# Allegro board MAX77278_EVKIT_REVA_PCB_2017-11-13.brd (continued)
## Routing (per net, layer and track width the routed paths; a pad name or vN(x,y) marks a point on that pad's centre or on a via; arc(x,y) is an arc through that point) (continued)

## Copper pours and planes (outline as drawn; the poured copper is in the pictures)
VBATT on TOP: 53.34,3.94 53.34,8 54.48,9.14 56.26,9.14 57.28,10.16 57.28,12.45 53.09,12.45 50.29,9.65 50.29,3.94
VBATT on INTERNAL2: 51.08,39.52 50.77,39.52 50.27,39.01 50.27,38.4 50.5,38.4 50.72,38.76 51.13,38.76 51.32,38.95 51.32,39.25 51.31,39.42 51.23,39.47
VBATT on INTERNAL3: 50.29,39.24 50.67,39.24 57.53,32.38 57.53,9.53 53.09,5.08 53.09,3.68 51.31,3.68 51.31,13.72 48.77,16.26 48.77,37.59 49.53,38.35 50.16,39.12
BST on TOP: 55.24,38.99 55.24,37.34 56.13,37.34 56.13,38.99
CHGIN on TOP: 48.49,40.77 49.71,40.77 49.96,40.51 49.96,40.44 49.53,40.01 48.49,40.01
CHGIN on TOP: 36.78,12.47 36.78,9.5 45.11,9.5 45.11,12.47
CHGIN on INTERNAL2: 49.15,40.74 50.09,40.74 50.11,40.72 50.11,40.23 49.56,39.67 48.49,39.67 48.49,40.08
CHGIN on INTERNAL3: 39.37,9.4 39.37,37.19 41.5,39.32 47.19,39.32 48.08,40.21 49.43,40.21 49.43,39.75 49.15,39.75 48.84,39.45 48.84,39.04 48.01,38.1 48.01,16.26 44.96,13.21 44.96,9.4
CS on TOP: 51.71,44.88 51.71,43.76 51.84,43.64 51.84,42.82 52.1,42.82 53.31,44.04 53.31,44.88
GROUND on TOP: 0.25,0.51 0.25,98.3 100.33,98.3 100.2,0.46 ; 16 cut-outs
GROUND on BOTTOM: 0.36,95.76 0.36,0.53 100.66,0.53 100.66,95.76 ; 31 cut-outs
GROUND on INTERNAL2: 11.84,0.81 0,0.76 0,96.27 100.5,96.27 100.43,0.81 ; 1 cut-out
IBATT_SNS on BOTTOM: 60.83,4.57 60.83,4.58 53.38,4.58 53.38,7.21 53.46,7.3 61.24,7.27 66.29,12.32 68.58,12.32 71.24,9.66 77.36,9.66 79.35,9.65 80,9 80.02,8.09 78.54,8.09 78.08,7.64 77.34,7.64 77.34,7.62 74.29,4.57
IN_SBB on TOP: 60.45,14.22 60.45,9.53 63.12,9.53 63.12,14.22
IN_SBB on BOTTOM: 51.59,40.54 51.59,39.12 52.7,39.12 52.7,40.54
IN_SBB on INTERNAL2: 51.69,40.21 51.69,40.17 51.36,39.84 51.36,39.46 51.79,39.04 52,39.04 52.26,39.29 52.26,39.85 51.89,40.21 51.7,40.21
IN_SBB on INTERNAL3: 58.04,32.13 51.31,38.86 51.31,39.88 51.69,40.26 52.83,40.26 62.36,30.73 62.36,24 63.63,22.61 63.63,9.53 58.04,9.53
INLDO on TOP: 55.52,42.44 55.52,43.41 66.52,54.41 80.72,54.41 81.66,55.35 84.56,55.35 84.56,52.53 84.53,52.5 79.25,52.5 79.04,52.7 66.93,52.7 56.67,42.44
LDO on TOP: 77.72,60.2 77.72,58.93 80.64,58.93 80.64,60.2
LDO on TOP: 53.37,43.05 53.37,43.26 53.82,43.71 53.82,44.42 54.28,44.88 54.28,45.03 54.41,45.16 54.41,45.67 54.61,45.87 54.61,46.99 67.82,60.2 80.95,60.22 80.98,60.2 81.05,60.2 81.79,60.93 88.65,60.93 89.2,60.38 91.67,60.38 91.67,57.45 88.26,57.45 87.53,58.19 68.83,58.17 56.39,45.72 55.27,45.72 55.27,45.62 55.22,45.57 55.09,45.57 54.81,45.29 54.81,44.78 54.58,44.55 54.58,44.09 54.18,43.69 54.18,43.18 54.05,43.05
LXA on TOP: 51.31,37.47 51.41,37.62 51.82,38.02 51.82,38.48 52.58,38.48 52.58,35.18 52.07,34.67 51.31,34.67
LXB on TOP: 53.85,34.67 53.47,35.05 53.47,37.26 53.29,37.44 53.29,38.61 54.74,38.61 54.74,34.67
SBB0 on TOP: 58.39,42.04 61.16,42.04 64.16,45.01 91.49,45.01 91.49,47.65 62.33,47.65 58.47,43.79 57.71,43 56.62,41.91 58.24,41.88
SBB1 on TOP: 58.67,41.05 58.7,40.34 61.37,37.69 91.49,37.69 91.49,39.93 91.29,40.13 63.35,40.13 61.82,41.66 59.28,41.66
SBB2 on TOP: 56.41,40.31 56.41,38.53 65.38,29.57 91.39,29.57 91.59,29.77 91.59,32.61 66.09,32.61 59.08,39.62 58.37,39.62 57.56,40.31
UNNAMED_1_CAPNP_I179_2 on TOP: 48.51,95.25 48.51,91.44 49.78,90.17 49.78,88.14 50.8,87.12 52.83,87.12 52.83,90.68 50.8,92.71 50.8,95.25
UNNAMED_1_HEADER2P_I176_1 on TOP: 54.61,95.25 54.61,87.12 56.39,87.12 56.39,95.25
UNNAMED_1_LED3P_I117_K on TOP: 51.82,51.82 51.82,46.99 53.34,46.99 53.34,48.26 53.85,48.77 53.85,51.82
UNNAMED_2_MAX14689_I1_NC1 on BOTTOM: 78.61,7.43 80.02,7.42 81.88,5.57 83.78,5.57 83.78,5.41 83.78,4.22 83.74,4.18 78.96,4.18 78.6,4.54 78.61,5.8
UNNAMED_6_EKCAPNP_I237_2 on BOTTOM: 91.82,45.09 96.6,45.06 96.6,50.85 91.82,50.88
UNNAMED_6_EKCAPNP_I261_2 on BOTTOM: 91.91,41.27 91.91,37.8 96.62,37.77 96.62,41.27 95.38,42.49 95.35,43.08 91.92,43.08
UNNAMED_6_EKCAPNP_I298_2 on BOTTOM: 91.95,35.92 91.94,30.45 96.52,30.45 96.55,35.92
UNNAMED_6_EKCAPNP_I332_2 on BOTTOM: 92.2,62.1 92.2,57.78 95.76,57.81 95.81,63.73 92.23,63.73
UNNAMED_6_EKRESSMD_I42_2 on BOTTOM: 93.47,51.44 91.44,51.44 91.14,51.13 89.66,51.13 89.66,52.2 90.17,52.7 93.47,52.7
UNNAMED_6_EKRESSMD_I273_2 on BOTTOM: 93.47,44.45 93.47,43.56 91.57,43.56 90.9,42.89 89.78,42.89 89.79,44.07 90.17,44.45
UNNAMED_6_EKRESSMD_I306_2 on BOTTOM: 93.6,36.32 91.69,36.32 91.33,35.96 90.04,35.95 90.04,37.21 93.6,37.21
UNNAMED_6_EKRESSMD_I340_2 on BOTTOM: 89.66,63.96 90.88,63.96 91.19,64.26 93.73,64.26 93.73,65.66 90.04,65.66 89.66,65.28
VSYS on TOP: 50.47,40.16 50.39,40.26 49.99,40.26 49.45,39.73 49.12,39.6 49.12,38.76 50.47,38.76
VSYS on TOP: 47.85,47.17 47.5,47.5 47.5,51.82 51.41,51.82 51.41,47.22 49.35,47.22 49.3,47.17
VSYS on BOTTOM: 46.53,8.48 45.9,9.12 45.9,31.85 47.24,33.2 47.24,39.83 47.27,39.81 47.24,41.1 45.77,42.57 45.8,52.22 51.05,52.22 51.05,52.2 51.03,48.03 51.03,46.28 51.05,40.44 51.05,38.18 51.56,37.67 51.56,9.32 50.72,8.48

Small or netless copper shapes (teardrops, artwork), in the pictures only: 5 on TOP, 5 on INTERNAL2

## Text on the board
Ref Des/Silkscreen Top: VIO | GND | SW8 | SW9 | NEN | POT | NTC | RES | VUSB | CHGIN | CS | CS-EN | 3.3V | SCL1 | SDA1 | IRNG | SBB1 | 1.8V | IBATT_SNS | AMUX | nEN | nIRQ | nRST | SCL | SDA | www.maximintegrated.com | 1-888-629-4642 | LB 11/17 | MAX77278 EV KIT | REVA
FAB_NOTES: NOTES: | FINISH: | TESTING: | MISCELLANEOUS: | TOOLING: | 15.  CHECK ALL THAT APPLY | 16.  VENDOR LOGO & DATE CODE REQUIRED IN INK ON BOTTOM SIDE ONLY. DATE CODE FORMAT MUST BE YYWW ONLY | 17.  FINAL ELECTRICAL TEST TO BE PERFORMED USING PROVIDED IPC-D-356A NETLIST OR ODB++ FORMAT FILE. | 18.  A TIME DOMAIN REFLECTOMETER REPORT FOR EACH IMPEDANCE CONTROLLED LAYER AND A CERTIFICATE | 24.  THIEVING: | 23.  FINISHED SURFACE CONTACTS AND FILLED VIAS TO BE FREE OF ANY PITS. SCRATCHES PROBE MARKS | 19.  FOR BLIND AND BURIED VIA INFORMATION REFER TO DRILL CHART. | 21.  ALL MICRO-VIAS LESS THAN 0.006 INCHES FHS WILL BE PLATED SHUT WITH COPPER, UNLESS OTHERWISE SPECIFIED. | 22.  FOR VIA SIZES XX.XX INCH USE NON CONDUCTIVE VIA FILL AND CAP | 13.  DRILL SIZES ARE FINISHED HOLE SIZES. ALL HOLES SHALL BE LOCATED WITHIN .005 DTP. | 14.  CHECK ALL THAT APPLY | 25.  PEMNUT | 9.  ALL TRACES FILLETED OPTION TO ENHANCE RELIABILITY AT PAD JUNCTIONS | 10.  LAYER TO LAYER REGISTRATIONS SHALL BE WITHIN .003 INCHES. | MATERIAL: | 11.  PLATING SPECIFICATION: | 12.  CHECK ALL THAT APPLY | 8.  IF STATED IN THE LAMINATION DIAGRAM, THE DIELECTRIC THICKNESS OF ANY | 1.  DIMENSIONS ARE IN INCHES (EXCEPT WHERE NOTED). | 3.  THE PCB SHALL BE FABRICATED TO IPC-6012, TYPE X, CLASS 2. | 4.  BOARD MATERIAL & CONSTRUCTION SHALL MEET THE REQUIREMENTS OF UL796 | 5.  OVERALL BOARD THICKNESS REFER TO LAMINATION DIAGRAM. TOLERANCE APPLIES | 6.  BOW & TWIST NOT TO EXCEED 0.0075 IN. (0.75%) PER LINEAR INCH. | 7.  PHOTO ETCH CIRCUITRY PER ENCLOSED GERBER RS274X OR ODB++ FORMAT FILE. | 2.  BOARD MATERIAL: | ( )  APPLY SILKSCREEN TO TOP SIDE USING A NON-CONDUCTIVE, WHITE EPOXY | ( )  OTHER ________________________ | (x)  APPLY SILKSCREEN TO BOTH SIDES USING A NON-CONDUCTIVE, WHITE EPOXY | (x)  GREEN SOLDERMASK OVER BARE COPPER/BARE GOLD (BOTH SIDES) WITH LIQUID PHOTO IMAGEABLE INK (LPI) | ( )  GREEN TAIYO PSR-4000 | ( )  FINGERS TO BE GOLD PLATED. | ( )  FINISH CONDUCTOR SURFACES: IMMERSION GOLD, 2-5 MICRO INCHES OVER | (X)  SUPPLIER MAY ADD THIEVING TO COMPENSATE FOR LOW COPPER DENSITY AREAS ON THIS DESIGN. | ( )  SUPPLIER MAY NOT ADD THIEVING TO COMPENSATE FOR LOW COPPER DENSITY AREAS ON THIS DESIGN. | ( )  NON-CONDUCTIVE EPOXY. FILL AND CAP ALL 0.XXXX INCH DRILLED VIAS. | ( )  SILVER. FILL AND CAP ALL 0.XXXX INCH DRILLED VIAS. | ( )  ELECTODEPOSITED HARD GOLD PLATE, TYPE 1 (99.7% MIN GOLD), GRADE C | (X) LEAD FREE AND RoHS COMPLIANT OR EQUIVALENT LEAD FREE PLATING | (REQUIRED UNLESS OTHERWISE SPECIFIED IN QUOTE) | THE PCB SHALL HAVE A VERIFICATION STAMP. | OF COMPLIANCE SHALL BE PROVIDED BY VENDOR AT TIME OF SHIPMENT. | ( )  PEMNUTS TO BE INSTALLED BY SUPPLIER. | ( )  PEMNUTS NOT TO BE INSTALLED BY SUPPLIER. | OR OTHER DEFORMITIES THAT COULD EFFECT THE APPERANCE AND PERFORMACE OF THE CONTACT | SURFACE. CONTACTS ARE TO BE AS FLAT AS POSSIBLE. NOT TO EXCEED +/- 0.001" OF FLATNESS. | (x)  FINISH CONDUCTOR SURFACES: IMMERSION GOLD, 3-8 MICRO INCHES OVER | (X)  STARTING AND FINISH COPPER WEIGHT FOR OUTER LAYERS TO BE (1 OZ). | ( )  STARTING COPPER WEIGHT FOR OUTER LAYERS CAN BE (1 OZ), THE FINISH COPPER WEIGHT IS (2 OZ). | ( )  FILLETED | (X)  NOT FILLETED | ( )  STARTING COPPER WEIGHT FOR OUTER LAYERS TO BE (2 OZ), THE FINISH COPPER WEIGHT IS (2 OZ)MINIMUM. | SO AS TO HINDER PROPER SOLDER WICKING. | (X)  FR4 ( RoHS COMPLIANT) OR EQUIVALENT | ( )  NELCO-4000-13 OR EQUIVALENT | ( )  370HR (RoHS COMPLIANT) OR EQUIVALENT | ( )  ROGERS 4350B | ( )  ROGERS 4003C | MINIMUM BARREL PLATING OF .001 IN. PLATED HOLES SHALL NOT BE ROUGH OR IRREGULAR | ( )  ISOLA-FR408HR | CONTROLLED IMPEDANCE LAYER IS FOR REFERENCE ONLY. FINAL ACCEPTANCE | SHALL BE DETERMINED BY THESE LAYERS HAVING A CHARACTERISTIC | IMPEDANCE OF +/-10% OHMS AS STATED IN THE LAMINATION DIAGRAM. THE | VENDOR CAN MAKE ADJUSTMENTS AS LONG AS THE STATED IMPEDANCE AND | OVERALL BOARD THICKNESS IS MAINTAINED. ANY ADJUSTMENT MADE TO TRACE | WIDTH OR SPACING MUST HAVE PRIOR WRITTEN APPROVAL FROM MAXIM. | WHERE SPACING PERMITS. | LEGEND TO LEGEND +/- 0.007 INCHES | WORKMANSHIP SHALL CONFORM TO IPC-A-600, CLASS 2, CURRENT REVISIONS. | WITH FLAMMABILITY RATING OF 94V-O. | AFTER ALL LAMINATION AND PLATING PROCESSES. IT IS TO BE MEASURED FROM | TOP PCB METAL TO BOTTOM PCB METAL UNLESS OTHERWISE SPECIFIED. | BOW & TWIST SHOULD BE MEASURED PER IPC-TM-650, METHOD 2.4.22. | DRILL LOCATION AND SIZE CONTROLLED BY EXCELLON CNC DRILL FILE. | THE STARTING WEIGHT CAN BE (<2 OZ) AS LONG AS THE FINISH COPPER WEIGHT IS (2 OZ). | UNLESS OTHERWISE SPECIFIED | THE STARTING WEIGHT CAN BE (0.5 OZ) AS LONG AS THE FINISH COPPER WEIGHT IS (2 OZ). | FOR OUTER LAYERS WHERE SPACING PREVENTS THE USE OF (1 OZ) AS A STARTING WEIGHT, | BASED INK PER ARTWORK. | PER ARTWORK. | (KNOOP HARDNESS 130-200), CLASS 1 (50-100 MICRO INCHES THICK) IN ACCORDANCE WITH MIL-G-45204C. | GENERAL SURFACING REQUIREMENTS MUST MEET ANSI/IPC-A-600(CURRENT REV) SECTION 4.0, | CLASS 3 (50-100 MICROINCHES THICK) OVER ELECTRODEPOSITED NICKEL PLATE | IN ACCORDANCE WITH ANSI/IPC-A-600D, SECTION 4.0, CLASS 3 (200-600 MICROINCHES THICK). | 118-236 MICRO INCHES MINIMUM OF ELECTROLESS NICKEL. | 100 MICRO INCHES MINIMUM OF ELECTROLESS NICKEL. | (USE CHECKED ITEMS FOR MATERIAL) | FOR OUTER LAYERS WHERE SPACING PREVENTS THE USE OF (1 OZ) AS A STARTING WEIGHT | THE STARTING WEIGHT CAN BE (0.5 OZ) AS LONG AS THE FINISH COPPER WEIGHT IS (1 OZ) | (USE CHECKED ITEMS FOR PLATING) | (USE CHECKED ITEMS FOR TOOLING) | UNLESS OTHERWISE SPECIFIED: | NOT TO SCALE | TEMPLATE REV 1.7 | TOLERANCES UNLESS OTHERWISE SPECIFIED | +/- | FRACTIONS | SEE NOTES | .XXX +/- .005 | .XX +/- .01 | DECIMALS | ANGLES | THE INFORMATION CONTAINED IN THIS DOCUMENT | IS PROPRIETARY TO MAXIM. THE INFORMATION IN | THIS DOCUMENT IS NOT TO BE SHOWN, REPRODUCED, | OR DISCLOSED TO ANYONE OUTSIDE OF MAXIM | WITHOUT PRIOR WRITTEN PERMISSION FROM MAXIM. | DRAWN BY: | CHECKED BY:ERIC RULE | APPR. BY: | LAKSHMI BHUJ | DATE: | DATE:11/13/2017 | 11/13/2017 | SIZE | E | DRAWING NO. | SHEET 1 OF 1 | REV | D | DESCRIPTION | REVISIONS | APPROVED | DATE | TITLE: | A | RELEASE | MAX77278 EVALUATION BOARD | FABRICATION DWG. | XX-XXXXXX-XX
User.25: FIGURE | SIZE | 8.0 | 12.01 | 35.43 | 37.4 | 39.37 | 45.28 | 62.99 | 70.87 | 125.0 | 41.34x25.59 | 51.18x27.56 | TOLERANCE | +3.0/-6.0 | +3.0/-3.0 | PLATED | NON-PLATED | ALL UNITS ARE IN MILS | QTY | 413 | 10 | 12 | 5 | 37 | 42 | 4 | 2 | NOTES | DRILL CHART: TOP to BOTTOM
User.27: FIGURE | SIZE | 8.0 | TOLERANCE | +3.0/-6.0 | PLATED | ALL UNITS ARE IN MILS | QTY | 20 | NOTES | DRILL CHART: INTERNAL2 to INTERNAL3
User.28: FIGURE | SIZE | 4.0 | TOLERANCE | +0.0/-4.0 | PLATED | ALL UNITS ARE IN MILS | QTY | 94 | NOTES | DRILL CHART: TOP to INTERNAL2
User.29: FIGURE | SIZE | 8.0 | TOLERANCE | +3.0/-6.0 | PLATED | ALL UNITS ARE IN MILS | QTY | 82 | NOTES | DRILL CHART: INTERNAL3 to BOTTOM
